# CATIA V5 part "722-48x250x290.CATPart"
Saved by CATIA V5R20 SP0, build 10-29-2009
Part number: 722-48x250x290
Definition: NONE
Nomenclature: 722-48x250x290
Source: Unknown
Description: 722-48x250x290
Bounding box of the stored display mesh (mm): x -24 to 24, y -23.825 to 23.825, z -232 to 58
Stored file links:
  C:\Users\Utente\Desktop\IO LAVORO\3D X SITO CF\X SITO\722\722-48x250x290.CATPart
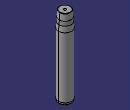
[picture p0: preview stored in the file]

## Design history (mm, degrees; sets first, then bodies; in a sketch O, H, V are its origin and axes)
Body1 "722-48x250x290" (main body)
  Solid1: solid without history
